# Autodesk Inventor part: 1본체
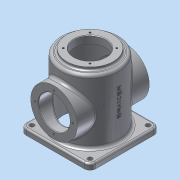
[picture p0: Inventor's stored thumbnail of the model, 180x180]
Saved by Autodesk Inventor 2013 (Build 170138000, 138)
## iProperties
Created: 2015-10
Part Number: 1본체
Material: 알루미늄 6061
Document SubType Name: Modeling
Designer: dgall
Density: 1 g/cm^3
Author: dgall
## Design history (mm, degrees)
sketch "스케치1"
  geometry: C1 r 50 at (0, 0); 1 further point
  constraints: 1 centre point, 1 coincident
  dimensions: "d0" = 100 diameter of C1
extrude "돌출1" new body sketch "스케치1" distance "d2" = 120; taper "d3" = 0 deg
sketch "스케치2"
  geometry: C1 r 50 at (0, 0) reference; C2 r 40 at (0, 0)
  constraints: 1 centre point, 1 coincident
  dimensions: "d4" = 80 diameter of C2
extrude "돌출2" join sketch "스케치2" distance "d6" = 5; taper "d7" = 0 deg
sketch "스케치3"
  geometry: L1 (-60, 60)-(60, 60); L2 (60, 60)-(60, -60); L3 (60, -60)-(-60, -60); L4 (-60, -60)-(-60, 60); C1 r 50 at (0, 0) reference; 2 further points
  constraints: 8 end point, 2 midpoint, 2 parallel, 2 perpendicular, 1 horizontal, 1 horizontal alignment, 1 vertical alignment
  dimensions: "d8" = 120 distance of L1.start L1.end
extrude "돌출3" join sketch "스케치3" distance "d11" = 10; taper "d12" = 0 deg
fillet "모깎기1" dims "d13" = 10
sketch "스케치4"
  geometry: A1 r 10 centre (-50, -50) between (-60, -50) and (-50, -60) reference; A2 r 10 centre (50, -50) between (50, -60) and (60, -50) reference; A3 r 10 centre (50, 50) between (60, 50) and (50, 60) reference; A4 r 10 centre (-50, 50) between (-50, 60) and (-60, 50) reference
hole "구멍1" sketch "스케치4" at (50, 50), (-50, 50), (-50, -50), (50, -50) diameter "d14" = 8; stored, may be unused: countersink angle "d18" = 90 deg, drill point angle "d20" = 118 deg; dims "d15" = 6, "d16" = 4, "d17" = 2, "d19" = 8
sketch "스케치5"
  geometry: C1 r 40 at (0, 0) reference; C2 r 27 at (0, 0)
  constraints: 1 centre point, 1 coincident
  dimensions: "d21" = 54 diameter of C2
extrude "돌출4" cut sketch "스케치5" distance "d23" = 13; taper "d24" = 0 deg
sketch "스케치6"
  geometry: L1 (-40, 0)-(0, 0); L2 (0, 0)-(-22.981, 22.981); 1 further point
  constraints: 4 end point, 1 coincident, 1 horizontal, 1 horizontal alignment, 1 other
  dimensions: "d26" = 45 deg angle of L1 L2; "d27" = 32.5 distance of L1.end L2.end
hole "구멍2" sketch "스케치6" at (-22.981, 22.981) diameter "d28" = 3.242; stored, may be unused: countersink angle "d32" = 90 deg, drill point angle "d34" = 118 deg; dims "d29" = 8, "d30" = 4, "d31" = 2, "d33" = 10
node "작업 평면1"
sketch "스케치7"
  geometry: L1 (-3.602, 45.113)-(-3.602, 94.887); L2 (-3.602, 94.887)-(3.602, 94.887); L3 (3.602, 94.887)-(3.602, 45.113); L4 (3.602, 45.113)-(-3.602, 45.113); L5 (-50, 0)-(50, 0) reference; 5 further points
  constraints: 3 midpoint, 2 vertical alignment, 1 horizontal alignment, 2 other
  dimensions: "d39" = 70 distance from line of L5 point (0, 70)
feature "엠보싱1" sketch "스케치7" dims "d2" = 120, "d3" = 0, "d13" = 10, "d40" = 0.5, "d41" = 0
sketch "스케치8"
  geometry: C1 r 40 at (0, 60); C2 r 27 at (0, 60); 1 further point
  constraints: 2 centre point, 1 coincident, 1 vertical alignment
  dimensions: "d43" = 60 distance of point (0, 0) C1.centre; "d44" = 80 diameter of C1; "d45" = 54 diameter of C2
extrude "돌출5" join sketch "스케치8" stored distance "d46" = 124; taper "d47" = 0 deg
extrude "돌출6" cut sketch "스케치8" stored distance "d48" = 124; taper "d49" = 0 deg
fillet "모깎기3" dims "d42" = 5
sketch "스케치9"
  geometry: C1 r 27 at (0, 0) reference; 2 further points
  constraints: 1 vertical alignment
  dimensions: "d50" = 32.5 distance of C1.centre point (0, -32.5)
hole "구멍3" sketch "스케치9" at (0, -32.5) diameter "d51" = 3.242; stored, may be unused: countersink angle "d55" = 90 deg, drill point angle "d57" = 118 deg; dims "d52" = 8, "d53" = 4, "d54" = 2, "d56" = 10
sketch "스케치10"
  geometry: C1 r 45 at (0, 0); 1 further point
  constraints: 1 centre point, 1 coincident
  dimensions: "d61" = 90 diameter of C1
extrude "돌출7" cut sketch "스케치10" distance "d63" = 112; taper "d64" = 0 deg
fillet "모깎기2" dims "d25" = 3
chamfer "모따기1" distance "d65" = 1; stored, may be unused: second distance "d66" = 2, angle "d67" = 45 deg
chamfer "모따기2" distance "d68" = 3; stored, may be unused: second distance "d69" = 2, angle "d70" = 45 deg
node "솔리드1"
pattern_circular "원형 패턴1" dims angle "d36" = 360 deg
pattern_circular "원형 패턴2" dims angle "d59" = 360 deg
mirror "대칭1"
